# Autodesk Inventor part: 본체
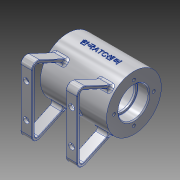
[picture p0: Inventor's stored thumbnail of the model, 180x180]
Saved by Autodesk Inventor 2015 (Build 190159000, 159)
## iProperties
Created: 2021-12
Part Number: 본체
Material: 알루미늄 6061
Document SubType Name: Modeling
Designer: pc-04
Density: 2.7 g/cm^3
Appearance: 알루미늄 - 평지
Mass: 310.255 g
Surface Area: 354.971 cm^2
Volume: 114.909 cm^3
Author: pc-04
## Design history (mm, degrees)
sketch "스케치1"
  geometry: L1 (-71.853, 0)-(122.253, 0); L2 (-35, 71)-(-35, 84); L3 (-35, 84)-(35, 84); L4 (35, 84)-(35, 71); L5 (35, 71)-(23, 71); L6 (23, 71)-(23, 69); L7 (23, 69)-(21, 69); L8 (21, 69)-(21, 76); L9 (21, 76)-(-21, 76); L10 (-21, 76)-(-21, 69); L11 (-21, 69)-(-23, 69); L12 (-23, 69)-(-23, 71); L13 (-23, 71)-(-35, 71); L14 (0, 0)-(0, 157.846); L15 (-71.853, 55)-(77.25, 55)
  constraints: 30 end point, 10 perpendicular, 3 point on line, 2 horizontal, 2 vertical, 1 collinear, 3 other
  dimensions: "d0" = 55 distance from line of L1 L15.end; "d1" = 28 diameter of L7 L15; "d2" = 32 diameter of L5 L15; "d3" = 58 diameter of L3 L15; "d4" = 42 diameter of L9 L15; "d5" = 42 distance of L8.end L9.end; "d6" = 70 distance of L2.end L3.end; "d7" = 12 distance of L4.end L5.end
revolve "회전1" sketch "스케치1" stored, may be unused: angle "d8" = 90 deg
node "작업 평면2"
  node "작업 평면1"
sketch "스케치2"
  geometry: C1 r 5 at (0, 0); 1 further point
  constraints: 1 centre point, 1 coincident
  dimensions: "d11" = 10 diameter of C1
extrude "돌출1" join sketch "스케치2" stored distance "d12" = 10; taper "d13" = 0 deg
sketch "스케치3"
  geometry: L1 (55, 0)-(24.93, -10.945); L2 (55, 52.445)-(55, -65.406); 1 further point
  constraints: 4 end point, 1 horizontal alignment, 1 point on line, 1 vertical
  dimensions: "d14" = 55 distance of point (0, 0) L1.start; "d15" = 70 deg angle of L1 L2; "d16" = 32 distance of L1.start L1.end
node "작업 평면3"
sketch "스케치4"
  geometry: C1 r 6 at (0, 0); 2 further points
  constraints: 1 centre point, 1 coincident
  dimensions: "d17" = 12 diameter of C1
extrude "돌출2" join sketch "스케치4" stored distance "d18" = 10; taper "d19" = 0 deg
node "작업 평면4"
sketch "스케치5"
  geometry: L1 (0, 40)-(0, -40); L2 (0, -40)-(39.614, -21.528); L3 (0, 40)-(39.614, 21.528); L4 (0, 0)-(65.899, 0); L5 (38.346, 18.809)-(3, 35.291); L6 (3, 35.291)-(3, -35.291); L7 (3, -35.291)-(38.346, -18.809); L8 (39.614, -21.528)-(38.346, -18.809); L9 (39.614, 21.528)-(38.346, 18.809); 1 further point
  constraints: 18 end point, 2 equal length, 1 coincident, 1 horizontal, 1 midpoint, 1 perpendicular, 1 vertical, 3 other
  dimensions: "d21" = 65 deg angle of L1 L2; "d22" = 80 distance of L1.start L1.end; "d23" = 3 distance between parallel lines of L3 L5; "d24" = 39 distance from line of L5.end L9
extrude "돌출3" join sketch "스케치5" stored distance "d25" = 12; taper "d26" = 0 deg
sketch "스케치6"
  geometry: L1 (0, 75.291)-(12, 75.291) reference; L2 (6, 75.291)-(6, -4.709); L3 (12, -4.709)-(0, -4.709) reference; L4 (6, 35.291)-(20.254, 35.291); 3 further points
  constraints: 4 end point, 3 midpoint, 2 point on line, 1 horizontal, 1 symmetric about line
  dimensions: "d27" = 36 distance of point (6, 17.291) point (6, 53.291)
hole "구멍1" sketch "스케치6" at (6, 53.291), (6, 17.291) diameter "d28" = 6; stored, may be unused: countersink angle "d32" = 90 deg, drill point angle "d34" = 118 deg; dims "d29" = 6, "d30" = 4, "d31" = 2, "d33" = 8
fillet "모깎기1" dims "d35" = 6, "d36" = 3
fillet "모깎기2" dims "d37" = 0.5
fillet "모깎기3" dims "d38" = 3
sketch "스케치7"
  geometry: A1 r 21 centre (0, 0) between (0, 21) and (21, 0); 3 further points
  constraints: 4 point on circle, 3 vertical alignment, 2 horizontal alignment, 1 centre point
  dimensions: "d39" = 42 diameter of A1; "d40" = 55 distance of point (0, -55) A1.centre
hole "구멍2" sketch "스케치7" at (0, 21), (21, 0), (0, -21), (-21, 0) diameter "d41" = 3.242; stored, may be unused: countersink angle "d45" = 90 deg, drill point angle "d47" = 118 deg; dims "d42" = 8, "d43" = 4, "d44" = 2, "d46" = 10
hole "구멍3" diameter "d50" = 5.188; stored, may be unused: countersink angle "d54" = 90 deg, drill point angle "d56" = 118 deg; dims "d48" = 10, "d49" = 10, "d51" = 12, "d52" = 4, "d53" = 2, "d55" = 25
hole "구멍4" diameter "d59" = 5.188; stored, may be unused: countersink angle "d63" = 90 deg, drill point angle "d65" = 118 deg; dims "d57" = 10, "d58" = 10, "d60" = 6, "d61" = 4, "d62" = 2, "d64" = 8
hole "구멍5" diameter "d68" = 3; stored, may be unused: countersink angle "d72" = 90 deg, drill point angle "d74" = 118 deg; dims "d66" = 10, "d67" = 10, "d69" = 6, "d70" = 4, "d71" = 2, "d73" = 25
fillet "모깎기4" dims "d75" = 1
fillet "모깎기5" dims "d76" = 0.3, "d77" = 3
chamfer "모따기1" distance "d78" = 1; stored, may be unused: second distance "d79" = 2, angle "d80" = 45 deg
sketch "스케치8"
  geometry: L1 (-26.869, 64.232)-(26.869, 64.232); L2 (26.869, 64.232)-(26.869, 45.768); L3 (26.869, 45.768)-(-26.869, 45.768); L4 (-26.869, 45.768)-(-26.869, 64.232); L5 (-26.869, 64.232)-(26.869, 64.232); L6 (26.869, 64.232)-(26.869, 45.768); L7 (26.869, 45.768)-(-26.869, 45.768); L8 (-26.869, 45.768)-(-26.869, 64.232); L9 (26.869, 64.232)-(-26.869, 45.768); 2 further points
  constraints: 10 end point, 2 coincident, 2 parallel, 1 horizontal, 1 midpoint, 1 perpendicular, 1 vertical alignment, 2 other
  dimensions: "d81" = 55 distance of point (0, 0) point (0, 55)
sketch "스케치9"
  geometry: A1 r 29.5 centre (55, 0) between (84.5, 0) and (25.5, 0); 1 further point
  constraints: 2 point on circle, 1 centre point, 1 horizontal alignment
  dimensions: "d82" = 55 distance of point (0, 0) A1.centre; "d83" = 59 diameter of A1
feature "돌출 곡면1" sketch "스케치9" dims "d84" = 45, "d85" = 0
extrude "돌출4" join sketch "스케치8" stored distance "d86" = 45; taper "d87" = 0 deg
node "솔리드1"
mirror "대칭1"
mirror "대칭2"
node "곡면1"
other parameters: "d9" = 55, "d10" = 32, "d20" = 24
